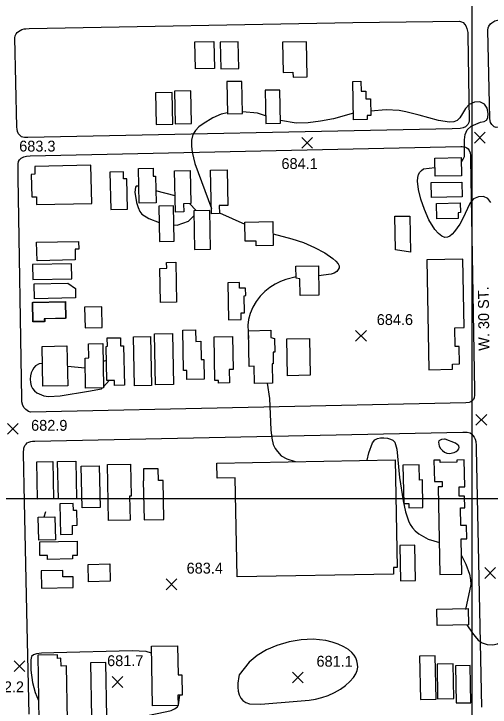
# Model space of a CAD drawing. Extents: x 79600 to 91800, y 75600 to 84400.
# Drawn here: x 83366 to 84026, y 78712 to 79671 of the extents above; entities that cross this region are included whole.
import ezdxf

# ---------------------------------------------------------------- set-up
doc = ezdxf.new("R2010")
doc.units = 0
for name, color, linetype in [('080-085$0$BLDG', 7, 'Continuous'), ('080-085$0$GRID', 7, 'Continuous'), ('080-085$0$INTER', 7, 'Continuous'), ('080-085$0$ROAD', 7, 'Continuous'), ('080-085$0$ROAD-NAME', 7, 'Continuous'), ('080-085$0$SPOTMARK', 7, 'Continuous'), ('080-085$0$SPOTS', 7, 'Continuous')]:
    doc.layers.add(name, color=color, linetype=linetype)

# ---------------------------------------------------------------- blocks, each defined once
blk = doc.blocks.new('080-085$0$SPOTS')
at = {"layer": '080-085$0$SPOTMARK'}
for p, q in [((-0.5, -0.5), (0.5, 0.5)), ((-0.5, 0.5), (0.5, -0.5))]:
    blk.add_line(p, q, dxfattribs=at)

msp = doc.modelspace()

# ---------------------------------------------------------------- linework, layer by layer
at = {"layer": '080-085$0$BLDG'}
for points in [[(83617.61, 79595.03), (83616.91, 79632.59), (83643.34, 79633.08), (83644.05, 79595.52)], [(83677.68, 79595.56), (83676.99, 79632.6), (83652.16, 79632.14), (83652.85, 79595.1)], [(83752.68, 79590.29), (83752.81, 79583.66), (83772.11, 79584.02), (83771.21, 79632.35), (83738.21, 79631.73), (83738.99, 79590.04)], [(83661.24, 79577.31), (83662.07, 79532.8), (83682.84, 79533.18), (83682.01, 79577.7)], [(83846.65, 79577.82), (83846.9, 79564.03), (83853.51, 79564.15), (83853.71, 79553.55), (83859.8, 79553.67), (83860.23, 79530.43), (83855.15, 79530.34), (83855.26, 79524.77), (83836.49, 79524.42), (83835.49, 79577.62)], [(83562.64, 79562.06), (83563.46, 79518.04), (83586.27, 79518.47), (83585.45, 79562.49)], [(83588.66, 79564.09), (83589.5, 79518.89), (83612.39, 79519.32), (83611.54, 79564.52)], [(83714.16, 79565.31), (83715.02, 79519.35), (83735.3, 79519.73), (83734.44, 79565.69)], [(83948.84, 79471.49), (83985.6, 79472.23), (83986.1, 79447.09), (83949.34, 79446.36)], [(83395.43, 79460), (83395.65, 79449.1), (83390.64, 79449), (83391.27, 79417.84), (83397.74, 79417.97), (83397.95, 79407.33), (83474.25, 79408.86), (83473.19, 79461.56)], [(83539.67, 79409.31), (83538.71, 79457.11), (83559.19, 79457.52), (83559.41, 79446.52), (83562.64, 79446.59), (83563.38, 79409.79)], [(83601.35, 79408.5), (83601.58, 79397.02), (83589.97, 79396.78), (83588.82, 79454.1), (83610.59, 79454.53), (83611.51, 79408.71)], [(83650.79, 79405.81), (83651.01, 79394.86), (83639.89, 79394.64), (83638.67, 79455.06), (83661.73, 79455.52), (83662.72, 79406.05)], [(83499.5, 79452.26), (83500.54, 79400.21), (83523.71, 79400.68), (83522.86, 79442.99), (83518.26, 79442.9), (83518.07, 79452.63)], [(83943.75, 79437.62), (83986.46, 79438.48), (83986.88, 79417.78), (83944.16, 79416.92)], [(83567.17, 79404.98), (83568.15, 79356.05), (83588.36, 79356.46), (83587.38, 79405.39)], [(83951.51, 79408.81), (83984.22, 79409.46), (83984.49, 79396.08), (83981.08, 79396.01), (83981.25, 79387.88), (83951.95, 79387.3)], [(83615.43, 79398.79), (83616.51, 79344.97), (83638.67, 79345.41), (83637.59, 79399.23)], [(83894.44, 79344.57), (83893.51, 79391.01), (83914.5, 79391.43), (83915.51, 79341.24)], [(83725.44, 79350.74), (83701.78, 79350.27), (83701.65, 79356.74), (83686.58, 79356.44), (83686.05, 79382.93), (83724.78, 79383.7)], [(83456.28, 79345.73), (83451.14, 79345.63), (83451.44, 79330.59), (83398.53, 79329.53), (83398.01, 79355.11), (83456.07, 79356.27)], [(83973.37, 79179.46), (83973.23, 79186.62), (83983.12, 79186.82), (83982.64, 79211.05), (83976.97, 79210.94), (83976.45, 79236.86), (83989.66, 79237.12), (83987.76, 79331.95), (83937.82, 79330.95), (83940.87, 79178.81)], [(83392.11, 79324.19), (83392.52, 79303.5), (83446.82, 79304.59), (83446.41, 79325.28)], [(83569.41, 79271.74), (83568.54, 79319.04), (83578.03, 79319.21), (83577.88, 79327.25), (83590.6, 79327.48), (83591.62, 79272.14)], [(83762.58, 79281.54), (83762.16, 79304.7), (83757.03, 79305.59), (83756.73, 79321.92), (83787.9, 79322.5), (83788.65, 79282.02)], [(83680.96, 79248.14), (83680.79, 79257.4), (83685.56, 79257.49), (83685.13, 79281.21), (83687.24, 79281.25), (83687.05, 79291.59), (83678.83, 79291.44), (83678.68, 79299.35), (83662.6, 79299.06), (83663.54, 79247.82)], [(83441.37, 79298.55), (83451.66, 79291.2), (83451.92, 79278.14), (83394.85, 79277), (83394.43, 79297.61)], [(83437.75, 79249.64), (83408.57, 79249.1), (83408.64, 79245.17), (83392.61, 79244.87), (83392.12, 79271.87), (83437.32, 79272.71)], [(83438.33, 79249.95), (83409.27, 79249.36), (83409.34, 79245.6), (83393.34, 79245.28), (83392.8, 79272.36), (83437.87, 79273.26)], [(83488.74, 79237.18), (83488.16, 79265.89), (83464.4, 79265.41), (83464.97, 79236.71)], [(83617.95, 79233.95), (83618.24, 79218.03), (83625.09, 79218.16), (83625.56, 79192.73), (83629.15, 79192.79), (83629.64, 79165.84), (83605.98, 79165.41), (83605.76, 79177.63), (83601.11, 79177.54), (83600.08, 79233.62)], [(83698.88, 79183.57), (83692.09, 79183.44), (83691.18, 79232.8), (83722.03, 79233.37), (83722.22, 79223.14), (83727.18, 79222.2), (83727.53, 79203.16), (83725.06, 79203.11), (83725.35, 79187.14), (83723.93, 79187.11), (83724.42, 79160.31), (83699.32, 79159.84)], [(83513.93, 79223.09), (83514.14, 79211.89), (83518.34, 79211.97), (83519.35, 79157.28), (83505.86, 79157.03), (83505.73, 79163.9), (83495.16, 79163.7), (83494.29, 79211.13), (83496.01, 79211.16), (83495.8, 79222.75)], [(83555.56, 79224.77), (83556.81, 79156.77), (83533.4, 79156.34), (83532.15, 79224.34)], [(83585.92, 79228.7), (83587.22, 79158.3), (83562.5, 79157.85), (83561.2, 79228.24)], [(83670.01, 79179.29), (83664.55, 79179.19), (83664.9, 79160.54), (83649.82, 79160.26), (83649.75, 79164), (83644.58, 79163.9), (83643.47, 79224.16), (83669.17, 79224.63)], [(83489.39, 79215.03), (83490.52, 79153.76), (83465.81, 79153.3), (83465.04, 79194.9), (83470.32, 79195), (83469.96, 79214.67)], [(83744.09, 79221.43), (83775.6, 79222.01), (83776.53, 79171.09), (83745.03, 79170.51)], [(83405.73, 79210.98), (83439.99, 79211.61), (83441, 79156.66), (83406.74, 79156.03)], [(83398.99, 78999.88), (83398.04, 79051.54), (83420.43, 79051.95), (83421.38, 79000.29)], [(83428.03, 79000.34), (83427.08, 79051.68), (83452.01, 79052.14), (83452.96, 79000.79)], [(83896.86, 78905.34), (83891.68, 78905.25), (83891.85, 78896.02), (83675.29, 78892.03), (83672.77, 79029.15), (83647.84, 79028.69), (83647.45, 79049.69), (83894.12, 79054.23)], [(83986.48, 78896.03), (83985.59, 78944.64), (83993.1, 78944.78), (83992.76, 78963.47), (83985, 78963.33), (83984.56, 78987.63), (83990.46, 78987.74), (83990.16, 79003.82), (83982.83, 79003.68), (83982.59, 79016.64), (83990.34, 79016.78), (83989.65, 79054.01), (83979.29, 79053.82), (83979.34, 79050.94), (83956.4, 79050.51), (83956.34, 79053.73), (83947.79, 79053.58), (83948.33, 79023.93), (83959.09, 79024.13), (83959.23, 79016.86), (83953.84, 79016.76), (83956.07, 78895.47)], [(83460.81, 78987.55), (83459.75, 79045.22), (83484.7, 79045.68), (83485.76, 78988.01)], [(83497.52, 78970.06), (83496.09, 79047.65), (83527.97, 79048.24), (83528.78, 79003.92), (83526.63, 79003.88), (83527.24, 78970.61)], [(83574.18, 78971.64), (83573.18, 79025.65), (83566.62, 79025.53), (83566.32, 79041.83), (83545.71, 79041.45), (83546.01, 79024.94), (83545.61, 79024.93), (83546.6, 78971.13)], [(83905.92, 78993.54), (83912.91, 78993.67), (83913.02, 78987.74), (83932.6, 78988.1), (83931.9, 79026.24), (83927.9, 79026.17), (83927.51, 79047.05), (83904.94, 79046.63)], [(83447.61, 78951.27), (83447.39, 78963.39), (83453.91, 78963.51), (83453.53, 78984), (83448.93, 78983.91), (83448.76, 78993.49), (83430, 78993.14), (83430.78, 78950.96)], [(83400.8, 78942.98), (83400.21, 78975.02), (83423.29, 78975.44), (83423.88, 78943.41)], [(83447.42, 78921.62), (83447.5, 78917.08), (83413, 78916.44), (83412.9, 78921.98), (83402.63, 78921.79), (83402.28, 78940.65), (83453.91, 78941.6), (83454.27, 78921.75)], [(83900.74, 78935.72), (83901.64, 78886.73), (83922.3, 78887.11), (83921.39, 78936.1)], [(83469.28, 78909.46), (83499.15, 78910.01), (83499.59, 78886.07), (83469.72, 78885.52)], [(83448.42, 78892.44), (83434.36, 78892.18), (83434.2, 78900.87), (83404.15, 78900.32), (83404.59, 78876.75), (83448.7, 78877.56)], [(83951.85, 78847.43), (83994.98, 78848.22), (83995.4, 78825.74), (83952.26, 78824.95)], [(83593.63, 78756.51), (83598.94, 78756.6), (83599.46, 78728.76), (83593.54, 78728.65), (83593.8, 78714.3), (83558.24, 78713.64), (83556.72, 78796.12), (83592.89, 78796.78)], [(83431.72, 78768.8), (83431.53, 78779.52), (83427.05, 78779.43), (83426.96, 78784.4), (83399.54, 78783.9), (83401.21, 78692.64), (83440.78, 78693.37), (83439.39, 78768.94)], [(83927.98, 78782.7), (83929.09, 78722.43), (83950.69, 78722.83), (83949.59, 78783.1)], [(83472.42, 78773.31), (83473.81, 78697.53), (83494.97, 78697.92), (83493.57, 78773.7)], [(83952, 78771.25), (83952.88, 78723.63), (83975.13, 78724.04), (83974.25, 78771.66)], [(83977.71, 78769.24), (83978.66, 78717.75), (83998.73, 78718.12), (83997.78, 78769.61)]]:
    msp.add_lwpolyline(points, close=True, dxfattribs=at)
at = {"layer": '080-085$0$GRID'}
for p, q in [((84000, 80000), (84000, 76000)), ((85000, 79000), (80000, 79000))]:
    msp.add_line(p, q, dxfattribs=at)
at = {"layer": '080-085$0$INTER'}
for p, q in [((83589.52, 79419.26), (83563.05, 79426.18)), ((83618.72, 79398.86), (83609.7, 79408.67)), ((83651, 79395.72), (83686.1, 79380.37)), ((83587.91, 79379.23), (83592.24, 79378.79)), ((83494.64, 79191.74), (83489.85, 79190.26)), ((83465.3, 79181.15), (83440.51, 79183.28)), ((83490.49, 79155.28), (83498.33, 79163.76)), ((83408.43, 78975.17), (83410.84, 78982.59))]:
    msp.add_line(p, q, dxfattribs=at)
for points in [[(83985.72, 79466.39), (83988.36, 79469.94), (83990.25, 79473.84), (83990.21, 79489.71), (83990.07, 79496.64), (83990.97, 79504.02), (83993.86, 79510.68), (83999.25, 79515.67), (84012.42, 79521.13), (84017.3, 79522.36), (84020.53, 79523.98), (84022.35, 79527.41), (84022.84, 79533.45), (84021.53, 79540.51), (84017.82, 79546.36), (84011.49, 79549.21), (84003.87, 79548.89), (83996.68, 79545.66), (83991.24, 79539.99), (83987.13, 79533.35), (83983.53, 79527.43), (83979.69, 79523.57), (83975.13, 79521.66), (83969.47, 79521.25), (83954.3, 79523.41), (83927.17, 79530.88), (83908.89, 79535.65), (83899.85, 79537.24), (83881.61, 79538.24), (83860.11, 79536.7)], [(83662.05, 79533.97), (83653.15, 79532.26), (83641.7, 79527.2), (83628.41, 79518.98), (83622.51, 79514.67), (83617.67, 79509.88), (83614.25, 79503.98), (83612.48, 79496.58), (83612.16, 79488.24), (83613, 79479.77), (83616.98, 79464.26), (83639.74, 79402.02)], [(83714.83, 79529.8), (83703.69, 79533.51), (83682.79, 79535.53)], [(83836.32, 79533.59), (83808.58, 79525.72), (83790.99, 79522.45), (83773.62, 79520.42), (83757.02, 79519.95), (83735.23, 79523.5)], [(84026.5, 79410.34), (84022.5, 79415.5), (84016.41, 79418.2), (84009.31, 79418.12), (84002.71, 79415.23), (83997.73, 79409.68), (83987.09, 79387.04), (83983.41, 79380.3), (83976.42, 79369.87), (83973.18, 79366.29), (83969.93, 79363.68), (83966.55, 79362.04), (83962.86, 79361.78), (83958.71, 79363.4), (83954.05, 79367.21), (83949.21, 79372.7), (83940.75, 79386.01), (83934.49, 79400.23), (83929.58, 79414.59), (83926.26, 79428.1), (83925.08, 79439.73), (83925.46, 79444.55), (83926.51, 79448.65), (83928.23, 79452), (83930.58, 79454.6), (83933.5, 79456.48), (83949.1, 79458.39)], [(83539.21, 79432.53), (83537.86, 79432.86), (83535.68, 79432.49), (83534.56, 79431.37), (83533.74, 79424.55), (83536.32, 79410.25), (83538.38, 79403.17), (83540.65, 79397.86), (83543.54, 79394.04), (83553.18, 79388.18), (83567.62, 79382.56)], [(83592.24, 79378.79), (83608.2, 79384.41), (83615.58, 79391.49)], [(83725.13, 79366.58), (83751.03, 79359.89), (83767.21, 79354.7), (83782.7, 79348.07), (83796.78, 79340.41), (83808.05, 79332.48), (83812.16, 79328.73), (83815.01, 79325.33), (83816.47, 79322.41), (83816.59, 79319.8), (83815.46, 79317.32), (83813.17, 79314.83), (83809.81, 79312.54), (83805.44, 79310.75), (83788.16, 79308.79)], [(83757, 79307.24), (83742.62, 79303.58), (83735.46, 79300.94), (83728.02, 79297.33), (83720.67, 79292.71), (83713.68, 79287.13), (83707.31, 79280.6), (83701.75, 79273.25), (83697.16, 79265.2), (83693.66, 79256.66), (83691.3, 79248.16), (83690.05, 79240.28), (83691.38, 79221.89)], [(83406.16, 79187.28), (83401.32, 79186.7), (83396.57, 79183.97), (83394.17, 79181.56), (83392.1, 79178.37), (83390.49, 79174.52), (83389.45, 79170.19), (83389.08, 79165.54), (83389.42, 79160.89), (83390.49, 79156.52), (83392.32, 79152.71), (83394.92, 79149.46), (83398.3, 79146.72), (83407.75, 79142.83), (83414.22, 79141.95), (83430.56, 79142.56), (83469.71, 79149.18)], [(83717.12, 79160.17), (83720.38, 79139.17), (83722.23, 79095.83), (83723.29, 79084), (83725.43, 79075.49), (83728.25, 79069.77), (83731.14, 79065.74), (83736.34, 79059.67), (83744.17, 79055.27), (83755.67, 79051.69)], [(83469.71, 79149.18), (83487.7, 79152.26), (83489.06, 79153.73)], [(83855.15, 79053.52), (83857.89, 79064.02), (83862.79, 79077.41), (83865.87, 79081.55), (83869.44, 79083.72), (83873.64, 79084.57), (83878.47, 79084.63), (83883.4, 79084.05), (83887.78, 79082.88), (83891.09, 79081.09), (83893.47, 79078.37), (83896.52, 79068.8), (83900.26, 79029.58), (83905.22, 78997.4), (83908.49, 78982.08), (83912.43, 78969.87), (83914.96, 78964.75), (83918.07, 78960.04), (83922.01, 78955.67), (83927.04, 78951.59), (83939.67, 78944.56), (83955.25, 78939.82)], [(83986.01, 78921.84), (83991.83, 78909.62), (83996.87, 78895.92), (83998.56, 78888.53), (83999.01, 78881.64), (83991.64, 78846.97)], [(83993.45, 78825.71), (84001.3, 78814.54), (84004.67, 78809.6), (84008.94, 78804.7), (84014.52, 78800.83), (84021.55, 78798.76), (84029.04, 78798.38), (84035.69, 78799.39), (84048.88, 78806.65), (84054.27, 78808.82), (84067.85, 78811.6), (84083.22, 78812.54), (84116.64, 78812.53), (84141.76, 78812.36), (84159.89, 78811.2), (84168.67, 78809.86), (84191.72, 78802.58)], [(83556.89, 78786.83), (83549.64, 78788.76), (83530.29, 78790.06), (83422.01, 78786.88), (83404.66, 78786.6), (83397.89, 78785.92), (83393.46, 78784.53), (83390.99, 78781.91), (83389.84, 78777.51), (83389.77, 78763.04), (83392.13, 78746.14), (83395.76, 78732.32), (83400.69, 78721.36)], [(83436.68, 78693.3), (83465.77, 78695.66), (83508.64, 78694.87), (83517.6, 78694.77), (83533.62, 78696.77), (83578.16, 78705.89), (83584.23, 78707.45), (83588.93, 78709.4), (83592.31, 78711.91), (83594.5, 78715.15), (83596.33, 78728.7)]]:
    msp.add_lwpolyline(points, dxfattribs=at)
for points in [[(83962.29, 79082.64), (83958.08, 79082.42), (83954.55, 79080.36), (83953.94, 79078.36), (83955.22, 79072.81), (83957.02, 79069.73), (83959.46, 79066.96), (83962.42, 79064.84), (83965.73, 79063.48), (83969.2, 79062.91), (83975.86, 79064.09), (83978.64, 79065.52), (83980.78, 79067.29), (83982.16, 79069.27), (83982.65, 79071.35), (83982.14, 79073.42), (83977.76, 79077.36), (83963.44, 79082.59)], [(83677.81, 78754.58), (83676.44, 78745.34), (83676.23, 78739.6), (83676.84, 78734.05), (83678.25, 78728.98), (83680.4, 78724.56), (83683.28, 78720.95), (83687.24, 78718.26), (83692.72, 78716.59), (83708.31, 78716.13), (83758.32, 78720.33), (83775.24, 78721.79), (83783.88, 78723.13), (83792.66, 78725.23), (83801.54, 78728.28), (83810.22, 78732.21), (83818.33, 78736.88), (83825.54, 78742.12), (83831.6, 78747.61), (83836.31, 78753), (83839.54, 78758), (83841.44, 78762.69), (83842.24, 78767.19), (83842.15, 78771.6), (83841.28, 78775.91), (83839.71, 78780.04), (83837.45, 78783.96), (83834.16, 78787.77), (83829.46, 78791.59), (83823.07, 78795.46), (83815.36, 78799.08), (83806.86, 78802.07), (83798.05, 78804.13), (83780.56, 78805.83), (83764.16, 78805.09), (83747.23, 78802.14), (83730.32, 78797.33), (83715.95, 78791.21), (83703.24, 78783.49), (83691.89, 78774.06), (83678.29, 78756.86)]]:
    msp.add_lwpolyline(points, close=True, dxfattribs=at)
at = {"layer": '080-085$0$ROAD'}
for points in [[(84336.62, 79520.31), (84033.85, 79514.04), (84031.05, 79515.03), (84029.37, 79516.44), (84027.97, 79517.85), (84026.15, 79520.8), (84025.6, 79522.91), (84025.33, 79526.55), (84022.3, 79648.63), (84022.59, 79651.58), (84023.72, 79654.1), (84025.97, 79657.18), (84028.08, 79658.86), (84030.47, 79660.53), (84032.16, 79661.23), (84037.63, 79662.76), (84047.17, 79663.01), (84057, 79662.98), (84336.62, 79670.19)], [(83387.86, 78702.07), (83384.69, 78823.31), (83381.24, 78996.17), (83379.75, 79063.52), (83380.05, 79070.12), (83381.6, 79073.76), (83383.43, 79076), (83384.98, 79077.4), (83387.22, 79078.52), (83389.89, 79079.49), (83392.14, 79079.76), (83395.51, 79079.9), (83987.77, 79092.55), (83990.58, 79092.54), (83993.95, 79092.25), (83997.73, 79091.4), (83999.55, 79090.13), (84001.79, 79087.88), (84003.47, 79085.63), (84004.72, 79082.68), (84005.56, 79079.31), (84006.1, 79073.98), (84006.09, 79069.21), (84013.65, 78711.97)]]:
    msp.add_lwpolyline(points, dxfattribs=at)
for points in [[(83835.72, 79659.25), (83983.19, 79660.81), (83985.85, 79660.24), (83988.09, 79658.97), (83990.33, 79656.44), (83991.73, 79654.33), (83993.26, 79650.82), (83994.51, 79645.48), (83994.64, 79641.97), (83996.41, 79523.13), (83996.13, 79520.6), (83994.86, 79518.08), (83993.03, 79515.98), (83991.48, 79514.58), (83988.39, 79513.33), (83984.18, 79512.64), (83972.95, 79512.25), (83385.74, 79500), (83381.11, 79500.15), (83379, 79500.58), (83377.18, 79501.15), (83374.52, 79503.12), (83372.84, 79505.23), (83371.59, 79508.18), (83370.9, 79511.69), (83370.76, 79514.21), (83368.02, 79637.97), (83368.31, 79640.92), (83369.58, 79643.44), (83370.99, 79645.54), (83372.82, 79646.8), (83375.21, 79648.19), (83377.59, 79649.31), (83380.82, 79650.28), (83383.07, 79650.56), (83387.56, 79650.82)], [(83372.39, 79444.9), (83372.31, 79463.56), (83372.74, 79466.78), (83374.15, 79469.31), (83376.68, 79471.68), (83380.05, 79473.36), (83383.98, 79474.19), (83389.03, 79474.6), (83984.95, 79487.38), (83986.77, 79487.38), (83988.74, 79487.23), (83991.26, 79486.8), (83993.22, 79485.82), (83994.9, 79484.55), (83996.58, 79482.16), (83997.69, 79478.65), (83998.24, 79475.28), (83998.37, 79469.81), (84004.07, 79150.31), (84004.05, 79143.44), (84003.34, 79140.07), (84002.35, 79137.69), (84001.08, 79136.01), (83998.98, 79134.33), (83996.31, 79133.22), (83991.82, 79132.95), (83389.59, 79120.18), (83386.78, 79121.17), (83384.68, 79122.3), (83382.86, 79123.85), (83380.76, 79126.1), (83378.67, 79129.19), (83377.7, 79134.24), (83377.57, 79138.31)]]:
    msp.add_lwpolyline(points, close=True, dxfattribs=at)

# ---------------------------------------------------------------- block references
at = {"layer": '080-085$0$SPOTMARK', "xscale": 15, "yscale": 15}
for p in [(84011.18, 79499.71), (83772.29, 79492.56), (83846.94, 79225.62), (84013.28, 79109.55), (83365.1, 79096.96), (84025.65, 78897.62), (83584.53, 78881.78), (83374.16, 78768.68), (83509.84, 78746.65), (83759.46, 78752.94)]:
    msp.add_blockref('080-085$0$SPOTS', p, dxfattribs=at)

# ---------------------------------------------------------------- texts
at = {"layer": '080-085$0$ROAD-NAME'}
msp.add_text('W. 30 ST.', height=15, rotation=90.61562, dxfattribs=at).set_placement((84024.51, 79204.98))
at = {"layer": '080-085$0$SPOTS'}
for s, p in [('683.3', (83373.87, 79480.64)), ('684.1', (83736.77, 79456.45)), ('684.6', (83868.63, 79240.62)), ('682.9', (83390.32, 79094.34)), ('683.4', (83605.54, 78896.78)), ('681.7', (83495.53, 78768.7)), ('681.1', (83785.25, 78767.94)), ('682.2', (83330.27, 78732.57))]:
    msp.add_text(s, height=15, dxfattribs=at).set_placement(p)

doc.saveas('drawing.dxf')
